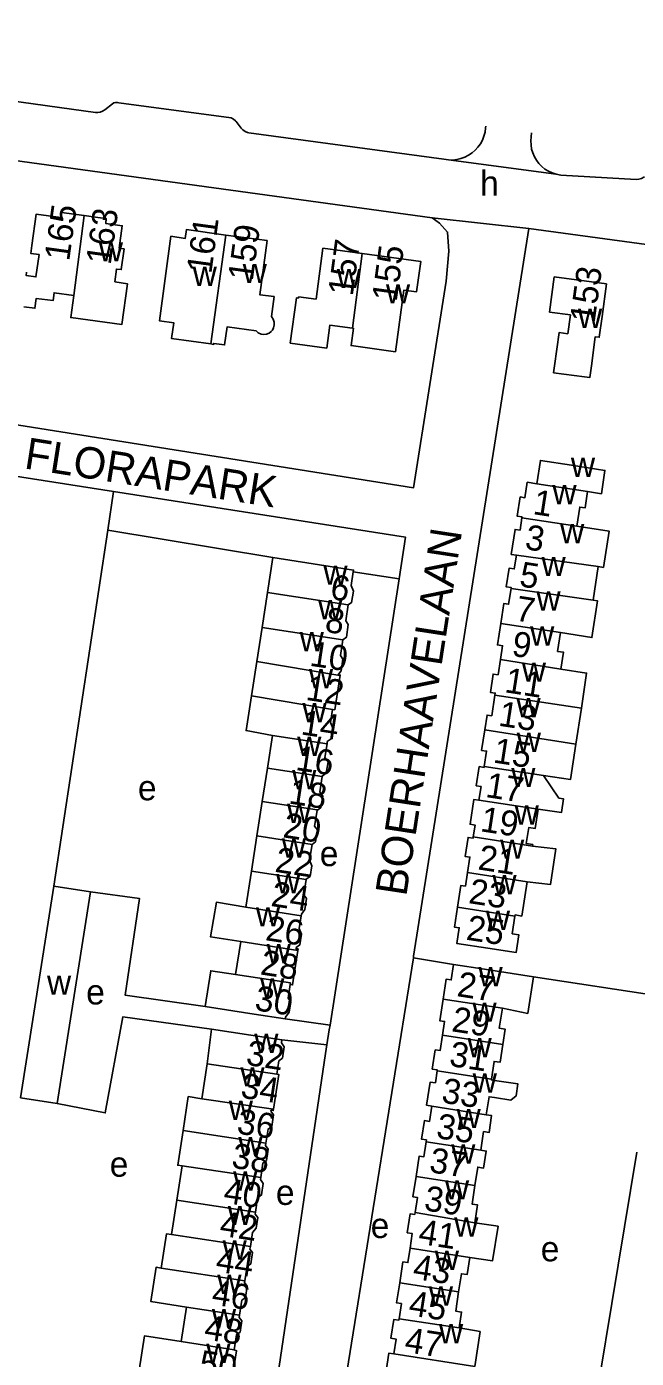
# Model space of a CAD drawing. Extents: x 161093 to 163177, y 379000 to 380904.
# Drawn here: x 161971.7 to 162069, y 380591.7 to 380804.1 of the extents above; entities that cross this region are included whole.
import ezdxf

# ---------------------------------------------------------------- set-up
doc = ezdxf.new("R2010")
doc.units = 0
for name, color, linetype in [('BLT_Basislijn', 7, 'Continuous'), ('BLT_Bebouwing', 7, 'Continuous'), ('BLT_Centroide', 7, 'Continuous'), ('BLT_Huisnummer', 7, 'Continuous'), ('BLT_Huisnummer_ tussenligend', 7, 'Continuous'), ('BLT_Onderverdeling_panden', 7, 'Continuous'), ('BLT_Straatnaam', 7, 'Continuous'), ('BLT_Vlakafsluiter', 7, 'Continuous')]:
    doc.layers.add(name, color=color, linetype=linetype)

msp = doc.modelspace()

# ---------------------------------------------------------------- linework, layer by layer
at = {"layer": 'BLT_Basislijn'}
for p, q in [((161944, 380795.73), (161982.7, 380790.46)), ((161985.43, 380791.84), (161984.2, 380790.88)), ((161986.42, 380791.99), (162004.35, 380789.6)), ((162005.15, 380788.99), (162005.94, 380787.96)), ((162045.01, 380788.28), (162044.96, 380787.97)), ((162052.3, 380787.21), (162052.25, 380786.56)), ((161984.69, 380723.8), (161985.62, 380729.97)), ((162011, 380719.43), (161984.69, 380723.8)), ((162031.18, 380716.05), (162023.85, 380717.15)), ((162020.14, 380644.86), (162031.18, 380716.05)), ((162039.85, 380654.53), (162033.44, 380655.58)), ((162072.89, 380649.45), (162052.6, 380652.57)), ((162012.98, 380645.84), (162020.14, 380644.86)), ((162012.46, 380642.49), (162019.64, 380641.72))]:
    msp.add_line(p, q, dxfattribs=at)
for points in [[(161815.82, 380804.14), (161900, 380793.04), (161955.5, 380784.75), (162036.45, 380773.62)], [(161985.43, 380791.84), (161985.66, 380791.98), (161985.92, 380792.06), (161986.2, 380792.06), (161986.42, 380791.99)], [(161982.7, 380790.46), (161983.09, 380790.44), (161983.47, 380790.5), (161983.83, 380790.64), (161984.2, 380790.88)], [(162004.35, 380789.6), (162004.73, 380789.37), (162005.06, 380789.09), (162005.15, 380788.99)], [(162005.94, 380787.96), (162006.25, 380787.66), (162006.61, 380787.41), (162007, 380787.24), (162007.19, 380787.18)], [(162007.19, 380787.18), (162038.29, 380782.98), (162039.05, 380782.87)], [(162044.96, 380787.97), (162044.87, 380787.31), (162044.7, 380786.67), (162044.46, 380786.05), (162044.14, 380785.46), (162043.75, 380784.92), (162043.3, 380784.43), (162042.8, 380783.99), (162042.24, 380783.62), (162041.65, 380783.32), (162041.02, 380783.09), (162040.38, 380782.94), (162039.71, 380782.86), (162039.05, 380782.87)], [(162052.25, 380786.56), (162052.19, 380785.91), (162052.21, 380785.26), (162052.31, 380784.61), (162052.49, 380783.98), (162052.75, 380783.38), (162053.08, 380782.82), (162053.47, 380782.3), (162053.93, 380781.83), (162054.43, 380781.42), (162054.99, 380781.07), (162055.58, 380780.8), (162056.2, 380780.6)], [(162056.2, 380780.6), (162056.95, 380780.46), (162068.97, 380779.73)], [(162068.97, 380779.73), (162069.4, 380779.78), (162069.83, 380779.9), (162070.22, 380780.1), (162070.33, 380780.18)], [(162036.45, 380773.62), (162037.62, 380772.81), (162038.9, 380771.36), (162039.11, 380768.34), (162038.66, 380763.52), (162033.44, 380730.54), (161945.64, 380744.48), (161940.61, 380712.05), (161930.4, 380713.71)], [(162051.87, 380771.94), (162033.48, 380655.83), (162033.44, 380655.58)], [(162140.7, 380759.86), (162051.87, 380771.94)], [(161957.99, 380734.3), (161985.62, 380729.97)], [(161985.62, 380729.97), (162032.21, 380722.67), (162031.18, 380716.05)], [(161984.69, 380723.8), (161976.06, 380667.03)], [(162000.24, 380647.8), (161987.44, 380649.63), (161989.76, 380665.04), (161981.9, 380666.11)], [(162033.44, 380655.58), (162019.61, 380569.67), (162019.47, 380568.79)], [(162001.24, 380644.21), (161987.08, 380646.16), (161984.29, 380630.85), (161976.58, 380632.33)], [(162020.14, 380644.86), (162020.02, 380644.09), (162019.64, 380641.72)], [(162009, 380569.91), (162019.42, 380640.32), (162019.64, 380641.72)], [(162039.84, 380567.66), (162059.15, 380564.39), (162069.07, 380624.57)]]:
    msp.add_lwpolyline(points, dxfattribs=at)
at = {"layer": 'BLT_Bebouwing'}
for p, q in [((162011, 380719.43), (162010.15, 380713.85)), ((162010.15, 380713.85), (162009.29, 380708.3)), ((162009.29, 380708.3), (162008.46, 380702.86)), ((162008.46, 380702.86), (162007.61, 380697.37)), ((162020.93, 380695.15), (162020.54, 380695.21)), ((162010.94, 380691.07), (162010.14, 380685.85)), ((162010.14, 380685.85), (162009.32, 380680.51)), ((162009.32, 380680.51), (162008.48, 380675.02)), ((162008.48, 380675.02), (162007.62, 380669.43)), ((162007.62, 380669.43), (162006.73, 380663.65)), ((161976.06, 380667.03), (161970.74, 380633.25)), ((161981.9, 380666.11), (161976.06, 380667.03)), ((161976.58, 380632.33), (161981.9, 380666.11)), ((162005.89, 380658.16), (162005.08, 380652.91)), ((162000.54, 380638.68), (162001.24, 380644.21)), ((161999.69, 380633.11), (162000.54, 380638.68)), ((161970.74, 380633.25), (161976.58, 380632.33)), ((161995.7, 380616.91), (161994.86, 380611.44)), ((161996.38, 380594.36), (161997.22, 380599.86))]:
    msp.add_line(p, q, dxfattribs=at)
for points in [[(161971.71, 380764.94), (161971.64, 380764.44), (161973.22, 380764.22), (161973.72, 380767.78), (161972.39, 380767.97), (161972.57, 380769.23), (161973.26, 380774.23), (161977.2, 380773.68), (161977.31, 380774.48), (161980.93, 380773.99)], [(161980.93, 380773.99), (161983.08, 380773.7), (161984.45, 380773.51), (161984.35, 380772.74), (161986.98, 380772.37), (161986.48, 380768.8), (161987.29, 380768.68), (161986.83, 380765.37), (161986.07, 380765.47), (161985.79, 380763.41)], [(162003.5, 380770.88), (161997.24, 380771.75), (161997.05, 380770.36), (161994.76, 380770.7), (161992.94, 380757.2), (161995.2, 380756.89), (161994.85, 380754.36), (162001.15, 380753.51)], [(162003.5, 380770.88), (162010.11, 380770.01), (162008.94, 380761.37), (162011.22, 380761.07), (162010.79, 380757.88), (162011.08, 380757.45), (162011.22, 380757.01), (162011.25, 380756.57), (162011.13, 380756.1), (162010.95, 380755.73), (162010.73, 380755.51), (162010.42, 380755.25), (162010.01, 380755.09), (162009.57, 380755.03), (162009.14, 380755.09), (162008.7, 380755.31), (162008.37, 380755.6), (162003.71, 380756.23), (162003.32, 380753.36), (162001.58, 380753.59), (162001.56, 380753.45), (162001.15, 380753.51)], [(162023.72, 380756.03), (162020.1, 380756.5), (162019.62, 380752.86), (162013.79, 380753.65), (162014.77, 380760.87), (162015.1, 380760.83), (162015.12, 380761.03), (162017.93, 380760.66), (162019.02, 380768.78), (162025.29, 380767.94)], [(162025.29, 380767.94), (162034.63, 380766.69), (162033.96, 380761.83), (162031.92, 380762.11), (162030.58, 380752.28), (162023.51, 380753.26), (162023.87, 380756.02), (162023.72, 380756.03)], [(162064.25, 380763.08), (162063.54, 380757.91), (162063.09, 380754.58), (162062.47, 380754.66), (162061.84, 380750), (162061.59, 380748.16), (162060.77, 380748.27), (162055.81, 380748.93), (162055.96, 380750), (162056.68, 380755.32), (162058.08, 380755.13), (162058.49, 380758.15), (162055.16, 380758.61), (162055.92, 380764.21), (162064.25, 380763.08)], [(161979.24, 380761.24), (161976.12, 380761.68), (161975.95, 380760.42), (161973.27, 380760.79), (161973.05, 380759.2), (161971.3, 380759.44)], [(161979.24, 380761.24), (161978.76, 380757.72), (161986.91, 380756.6), (161987.81, 380763.13), (161985.79, 380763.41)], [(162053.13, 380731.22), (162053.71, 380734.93), (162058.65, 380734.17), (162064.01, 380733.34), (162063.44, 380729.62), (162061.24, 380729.96)], [(162050.77, 380725.8), (162050.79, 380725.92), (162050.01, 380726.04), (162050.48, 380729.1), (162051.23, 380728.98), (162051.61, 380731.45), (162053.13, 380731.22)], [(162061.24, 380729.96), (162060.85, 380727.37), (162059.99, 380727.5), (162059.52, 380724.44)], [(162049.87, 380719.81), (162049.06, 380719.93), (162049.68, 380723.94), (162050.46, 380723.82), (162050.77, 380725.8)], [(162059.52, 380724.44), (162064.66, 380723.65), (162063.77, 380717.86), (162062.95, 380717.99)], [(162023.85, 380717.15), (162023.89, 380717.45), (162011, 380719.43)], [(162049.02, 380714.48), (162049.05, 380714.64), (162048.27, 380714.76), (162048.73, 380717.75), (162049.53, 380717.62), (162049.87, 380719.81)], [(162023.85, 380717.15), (162023.52, 380714.98), (162023.87, 380714.08), (162023.59, 380712.26), (162023.05, 380711.87)], [(162062.95, 380717.99), (162062.13, 380712.62)], [(162047.39, 380708.94), (162047.88, 380712.11), (162048.64, 380711.99), (162049.02, 380714.48)], [(162062.13, 380712.62), (162062.84, 380712.51), (162061.93, 380706.67), (162056.93, 380707.46)], [(162023.05, 380711.87), (162022.65, 380709.33), (162023.06, 380708.77), (162022.75, 380706.73), (162022.18, 380706.31)], [(162047.34, 380703.16), (162047.68, 380705.36), (162046.86, 380705.49), (162047.39, 380708.94)], [(162022.18, 380706.31), (162021.79, 380703.8), (162022.21, 380703.24), (162021.92, 380701.39), (162021.4, 380700.7)], [(162056.97, 380701.63), (162057.41, 380704.32), (162056.46, 380704.47), (162056.93, 380707.46)], [(162046.45, 380697.5), (162046.5, 380697.81), (162045.72, 380697.93), (162046.17, 380700.85), (162046.96, 380700.73), (162047.34, 380703.16)], [(162021.4, 380700.7), (162021.78, 380700.69), (162020.93, 380695.15)], [(162060.24, 380695.42), (162061.08, 380701), (162056.97, 380701.63)], [(162007.61, 380697.37), (162006.76, 380691.83), (162010.94, 380691.07)], [(162044.82, 380691.96), (162045.19, 380694.32), (162045.94, 380694.21), (162046.45, 380697.5)], [(162020.54, 380695.21), (162020.23, 380693.14), (162020.58, 380692.23), (162020.32, 380690.51), (162019.71, 380690.07), (162019.66, 380689.73)], [(162059.37, 380689.68), (162060.24, 380695.42)], [(162044.74, 380686.13), (162045.12, 380688.56), (162044.32, 380688.68), (162044.82, 380691.96)], [(162019.66, 380689.73), (162019.32, 380687.53), (162019.82, 380686.85), (162019.54, 380685.04), (162018.88, 380684.56), (162018.88, 380684.51)], [(162054.18, 380684.68), (162058.51, 380684.02), (162059.37, 380689.68)], [(162043.9, 380680.72), (162044.23, 380682.91), (162043.48, 380683.03), (162043.95, 380686.08), (162044.72, 380685.97), (162044.74, 380686.13)], [(162018.88, 380684.51), (162018.5, 380682.04), (162018.97, 380681.39), (162018.69, 380679.56), (162018.07, 380679.1)], [(162053.34, 380679.32), (162057.06, 380678.75), (162057.4, 380680.94), (162056.66, 380681.05), (162054.18, 380684.68)], [(162042.99, 380674.86), (162043.28, 380676.76), (162042.49, 380676.88), (162043.1, 380680.84), (162043.9, 380680.72)], [(162018.07, 380679.1), (162017.68, 380676.58), (162018.13, 380675.98), (162017.84, 380674.1), (162017.27, 380673.68)], [(162052.44, 380673.39), (162052.48, 380673.65), (162051.45, 380673.8), (162051.84, 380676.36), (162052.86, 380676.2), (162053.34, 380679.32)], [(162042.08, 380669.21), (162042.45, 380671.64), (162041.7, 380671.75), (162042.16, 380674.79), (162042.96, 380674.67), (162042.99, 380674.86)], [(162017.27, 380673.68), (162016.88, 380671.18), (162017.24, 380670.27), (162016.97, 380668.57), (162016.36, 380668.11), (162016.36, 380668.09)], [(162051.59, 380667.73), (162055.31, 380667.27), (162056.18, 380672.95), (162052.44, 380673.39)], [(162016.36, 380668.09), (162015.97, 380665.61), (162016.4, 380665.03), (162016.13, 380663.27), (162015.57, 380662.57), (162015.53, 380662.3)], [(162040.49, 380663.66), (162041.02, 380667.14), (162041.74, 380667.03), (162042.08, 380669.21)], [(162049.64, 380662.24), (162049.67, 380662.42), (162050.74, 380662.25), (162051.59, 380667.73)], [(162006.73, 380663.65), (162002.01, 380664.44), (162001.06, 380658.95), (162005.89, 380658.16)], [(162049.64, 380662.24), (162049.21, 380659.42), (162050.26, 380659.26), (162049.82, 380656.42), (162045.31, 380657.11), (162040.37, 380657.87), (162040.75, 380660.37), (162040, 380660.49), (162040.49, 380663.66)], [(162015.53, 380662.3), (162015.22, 380660.27), (162015.58, 380659.34), (162015.32, 380657.64), (162014.75, 380657.22), (162014.72, 380657.04), (162015.04, 380656.99), (162015, 380656.76)], [(162015, 380656.76), (162014.16, 380651.25), (162013.79, 380651.34)], [(162005.08, 380652.91), (162001.11, 380653.52), (162000.24, 380647.8)], [(162039.85, 380654.53), (162039.47, 380652.06), (162038.68, 380652.18), (162038.19, 380649)], [(162052.6, 380652.57), (162044.79, 380653.77), (162039.85, 380654.53)], [(162013.79, 380651.34), (162013.45, 380649.17), (162013.9, 380648.57), (162013.64, 380646.89), (162013.02, 380646.12), (162012.98, 380645.84)], [(162047.64, 380647.55), (162051.69, 380646.7), (162052.6, 380652.57)], [(162038.19, 380649), (162037.66, 380645.55), (162038.42, 380645.43), (162038.09, 380643.23)], [(162000.24, 380647.8), (162008.04, 380646.6), (162012.98, 380645.84)], [(162047.71, 380641.74), (162048.09, 380644.2), (162047.14, 380644.35), (162047.64, 380647.55)], [(162001.24, 380644.21), (162007.52, 380643.25), (162012.46, 380642.49)], [(162012.46, 380642.49), (162012.38, 380642), (162012.83, 380641.39), (162012.55, 380639.58), (162011.96, 380639.14), (162011.63, 380637)], [(162038.09, 380643.23), (162037.71, 380640.78), (162036.93, 380640.9), (162036.46, 380637.83), (162037.26, 380637.7), (162037.24, 380637.56)], [(162045.89, 380636.23), (162046.33, 380639.05), (162047.27, 380638.91), (162047.71, 380641.74)], [(162011.63, 380637), (162011.97, 380636.98), (162011.12, 380631.45)], [(162037.24, 380637.56), (162036.95, 380635.65), (162036.14, 380635.77), (162035.55, 380632.07), (162036.36, 380631.91)], [(162045.08, 380630.56), (162045.52, 380633.42), (162046.36, 380633.29), (162048.97, 380632.89), (162049.84, 380633.55), (162050.13, 380635.46), (162046.77, 380635.97), (162045.88, 380636.11), (162045.89, 380636.23)], [(161996.69, 380628.05), (161997.52, 380633.45), (161999.69, 380633.11)], [(162036.36, 380631.91), (162035.99, 380629.49), (162035.21, 380629.61), (162034.76, 380626.65), (162035.53, 380626.53), (162035.49, 380626.25)], [(162011.12, 380631.45), (162011.08, 380631.22), (162010.73, 380631.27), (162010.71, 380631.1), (162011.12, 380630.53), (162010.84, 380628.68), (162010.25, 380628.25), (162009.91, 380626.02)], [(162044.18, 380624.91), (162044.63, 380627.85), (162045.51, 380627.71), (162045.93, 380630.42), (162045.08, 380630.56)], [(161996.55, 380622.39), (161995.84, 380622.5), (161996.69, 380628.05)], [(162009.91, 380626.02), (162009.85, 380625.64), (162010.29, 380625.04), (162010.02, 380623.27), (162009.43, 380622.84), (162009.08, 380620.52)], [(162035.49, 380626.25), (162035.12, 380623.84), (162034.37, 380623.96), (162033.87, 380620.71)], [(162043.26, 380619.26), (162043.71, 380622.19), (162044.64, 380622.04), (162045.06, 380624.76), (162044.18, 380624.91)], [(161995.7, 380616.91), (161996.55, 380622.39)], [(162009.08, 380620.52), (162009.03, 380620.22), (162009.49, 380619.58), (162009.21, 380617.77), (162008.59, 380617.31), (162008.24, 380615.03)], [(162033.87, 380620.71), (162033.37, 380617.46), (162034.08, 380617.35), (162033.71, 380614.94)], [(162043.26, 380613.33), (162043.69, 380616.15), (162042.81, 380616.29), (162043.26, 380619.26)], [(162008.24, 380615.03), (162008.2, 380614.71), (162008.61, 380614.15), (162008.35, 380612.47), (162007.77, 380611.74), (162007.43, 380609.53)], [(162033.71, 380614.94), (162033.67, 380614.65), (162032.93, 380614.76), (162032.46, 380611.72), (162033.27, 380611.59), (162032.92, 380609.27)], [(162042.43, 380607.8), (162046.08, 380607.25), (162046.96, 380612.77), (162043.26, 380613.33)], [(161993.22, 380606.09), (161994.06, 380611.56), (161994.86, 380611.44)], [(162007.43, 380609.53), (162007.37, 380609.1), (162007.76, 380608.57), (162007.48, 380606.76), (162006.92, 380606.34), (162006.56, 380604.04)], [(162032.92, 380609.27), (162032.56, 380606.96), (162031.78, 380607.08), (162031.26, 380603.73)], [(162040.66, 380602.28), (162041.11, 380605.19), (162042.01, 380605.05), (162042.43, 380607.8)], [(161997.22, 380599.86), (161991.56, 380600.74), (161992.4, 380606.21), (161993.22, 380606.09)], [(162006.56, 380604.04), (162006.52, 380603.76), (162006.94, 380603.18), (162006.67, 380601.39), (162006.06, 380600.95), (162005.69, 380598.56)], [(162031.26, 380603.73), (162030.77, 380600.54), (162031.52, 380600.43), (162031.15, 380598.01)], [(162040.74, 380596.54), (162041.13, 380599.07), (162040.19, 380599.22), (162040.66, 380602.28)], [(162005.69, 380598.56), (162005.64, 380598.21), (162006.05, 380597.65), (162005.78, 380595.88), (162005.21, 380595.46), (162004.84, 380593.07)], [(162031.15, 380598.01), (162031.11, 380597.75), (162030.32, 380597.87), (162029.86, 380594.9), (162030.68, 380594.77), (162030.31, 380592.38)], [(162043.22, 380590.39), (162044.08, 380595.95), (162040.74, 380596.54)], [(161992.58, 380589.37), (161989.71, 380589.81), (161990.55, 380595.29), (161996.38, 380594.36)], [(162004.84, 380593.07), (162005.24, 380592.91), (162004.36, 380587.52)], [(162030.31, 380592.38), (162029.52, 380592.5), (162028.93, 380588.62), (162029.68, 380588.51), (162029.41, 380586.75)]]:
    msp.add_lwpolyline(points, dxfattribs=at)
at = {"layer": 'BLT_Onderverdeling_panden'}
for p, q in [((161979.24, 380761.24), (161980.93, 380773.99)), ((162003.5, 380770.88), (162001.15, 380753.51)), ((162025.29, 380767.94), (162023.72, 380756.03)), ((162053.13, 380731.22), (162061.24, 380729.96)), ((162059.52, 380724.44), (162050.77, 380725.8)), ((162062.95, 380717.99), (162049.87, 380719.81)), ((162023.05, 380711.87), (162010.15, 380713.85)), ((162062.13, 380712.62), (162049.02, 380714.48)), ((162022.18, 380706.31), (162009.29, 380708.3)), ((162056.93, 380707.46), (162047.39, 380708.94)), ((162021.4, 380700.7), (162008.46, 380702.86)), ((162056.97, 380701.63), (162047.34, 380703.16)), ((162020.54, 380695.21), (162007.61, 380697.37)), ((162060.24, 380695.42), (162046.45, 380697.5)), ((162059.37, 380689.68), (162044.82, 380691.96)), ((162019.66, 380689.73), (162010.94, 380691.07)), ((162018.88, 380684.51), (162010.14, 380685.85)), ((162053.34, 380679.32), (162043.9, 380680.72)), ((162017.27, 380673.68), (162008.48, 380675.02)), ((162052.44, 380673.39), (162042.99, 380674.86)), ((162016.36, 380668.09), (162007.62, 380669.43)), ((162051.59, 380667.73), (162042.08, 380669.21)), ((162015.53, 380662.3), (162006.73, 380663.65)), ((162049.64, 380662.24), (162040.49, 380663.66)), ((162015, 380656.76), (162005.89, 380658.16)), ((162047.64, 380647.55), (162038.19, 380649)), ((162047.71, 380641.74), (162038.09, 380643.23)), ((162011.63, 380637), (162000.54, 380638.68)), ((162045.89, 380636.23), (162037.24, 380637.56)), ((162011.12, 380631.45), (161999.69, 380633.11)), ((162045.08, 380630.56), (162036.36, 380631.91)), ((162009.91, 380626.02), (161996.69, 380628.05)), ((162044.18, 380624.91), (162035.49, 380626.25)), ((162009.08, 380620.52), (161996.55, 380622.39)), ((162043.26, 380619.26), (162033.87, 380620.71)), ((162008.24, 380615.03), (161995.7, 380616.91)), ((162043.26, 380613.33), (162033.71, 380614.94)), ((162007.43, 380609.53), (161994.86, 380611.44)), ((162042.43, 380607.8), (162032.92, 380609.27)), ((162006.56, 380604.04), (161993.22, 380606.09)), ((162040.66, 380602.28), (162031.26, 380603.73)), ((162005.69, 380598.56), (161997.22, 380599.86)), ((162040.74, 380596.54), (162031.15, 380598.01)), ((162004.84, 380593.07), (161996.38, 380594.36)), ((162043.22, 380590.39), (162030.31, 380592.38))]:
    msp.add_line(p, q, dxfattribs=at)
for points in [[(162054.18, 380684.68), (162044.74, 380686.13)], [(162018.07, 380679.1), (162018.08, 380679.17), (162009.32, 380680.51)], [(162013.79, 380651.34), (162013.82, 380651.57), (162005.08, 380652.91)]]:
    msp.add_lwpolyline(points, dxfattribs=at)
at = {"layer": 'BLT_Vlakafsluiter'}
for p, q in [((162056.2, 380780.6), (162039.05, 380782.87)), ((162036.45, 380773.62), (162051.87, 380771.94))]:
    msp.add_line(p, q, dxfattribs=at)

# ---------------------------------------------------------------- texts
at = {"layer": 'BLT_Centroide'}
for s, p in [('h', (162044.09, 380777.15)), ('w', (161983.25, 380766.67)), ('w', (161998.22, 380762.77)), ('w', (162006.2, 380763.22)), ('w', (162021.22, 380762.42)), ('w', (162029.06, 380759.97)), ('w', (162059.7, 380756.05)), ('w', (162058.57, 380732.28)), ('w', (162055.62, 380727.94)), ('w', (162056.85, 380721.72)), ('w', (162053.88, 380716.47)), ('w', (162019.08, 380715.09)), ('w', (162018.24, 380709.59)), ('w', (162053.07, 380710.97)), ('w', (162052.06, 380705.38)), ('w', (162015.3, 380704.5)), ('w', (162050.74, 380699.62)), ('w', (162016.77, 380698.59)), ('w', (162015.73, 380693.16)), ('w', (162049.87, 380693.94)), ('w', (162049.93, 380688.41)), ('w', (162014.9, 380687.78)), ('w', (162014.09, 380682.47)), ('w', (162049.05, 380682.81)), ('e', (161989.49, 380680.71)), ('w', (162013.28, 380677.09)), ('w', (162049.59, 380676.84)), ('w', (162012.44, 380671.56)), ('w', (162047.27, 380671.38)), ('e', (162018.5, 380670.21)), ('w', (162011.54, 380665.88)), ('w', (162046.04, 380665.72)), ('w', (162008.3, 380660.59)), ('w', (162045, 380660.03)), ('w', (162010.02, 380654.72)), ('w', (162043.82, 380651.03)), ('w', (161974.98, 380649.69)), ('e', (161981.23, 380648.14)), ('w', (162008.99, 380649.25)), ('w', (162042.86, 380645.38)), ('w', (162008.05, 380640.41)), ('w', (162042.08, 380639.72)), ('w', (162005.83, 380635.06)), ('w', (162042.9, 380634.06)), ('w', (162003.98, 380629.72)), ('w', (162040.33, 380628.41)), ('w', (162005.51, 380623.91)), ('w', (162039.47, 380622.75)), ('e', (161984.99, 380620.66)), ('w', (162004.69, 380618.44)), ('e', (162011.5, 380616.16)), ('w', (162038.48, 380617.03)), ('w', (162003.82, 380612.94)), ('e', (162026.63, 380610.88)), ('w', (162039.95, 380611.09)), ('w', (162002.99, 380607.44)), ('w', (162036.85, 380605.78)), ('e', (162053.76, 380607.16)), ('w', (162002.15, 380601.94)), ('w', (162035.9, 380600.09)), ('w', (162001.29, 380596.47)), ('w', (162037.52, 380594.09)), ('w', (162000.39, 380590.94))]:
    msp.add_text(s, height=4, dxfattribs=at).set_placement(p)
at = {"layer": 'BLT_Huisnummer'}
for s, rotation, p in [('165', 82.1094, (161978.52, 380766.63)), ('163', 82.1023, (161985.14, 380766.03)), ('161', 82.3132, (162001.2, 380764.61)), ('159', 82.3092, (162007.8, 380763.45)), ('157', 82.3009, (162023.76, 380761.05)), ('155', 82.3158, (162030.77, 380760.15)), ('153', 82.2551, (162062.35, 380756.75)), ('1', 351.1717, (162052.38, 380726.39)), ('5', 351.1719, (162050.21, 380714.87)), ('6', 351.2741, (162020.02, 380712.85)), ('9', 351.1733, (162049, 380703.79)), ('10', 351.2792, (162016.76, 380702.2)), ('13', 351.177, (162046.88, 380692.63)), ('14', 351.2785, (162015.37, 380691.24)), ('17', 351.2573, (162044.82, 380681.25)), ('18', 351.2759, (162013.41, 380680.22)), ('22', 351.2773, (162011.21, 380669.32)), ('21', 351.2418, (162043.61, 380669.7)), ('26', 351.276, (162009.71, 380658.41)), ('25', 351.2494, (162041.73, 380658.49)), ('27', 351.2494, (162040.25, 380649.48)), ('30', 351.2687, (162007.98, 380647.25)), ('32', 351.2748, (162006.59, 380638.53)), ('31', 351.2489, (162039.02, 380638.36)), ('36', 351.2752, (162005.12, 380627.58)), ('35', 351.2479, (162036.95, 380626.85)), ('40', 351.2791, (162003, 380616.53)), ('39', 351.2464, (162035.01, 380615.33)), ('44', 351.2772, (162001.76, 380605.55)), ('43', 351.243, (162033.22, 380604.4)), ('48', 351.2719, (161999.92, 380594.74)), ('47', 351.2479, (162031.89, 380592.72))]:
    msp.add_text(s, height=4, rotation=rotation, dxfattribs=at).set_placement(p)
at = {"layer": 'BLT_Huisnummer_ tussenligend'}
for s, rotation, p in [('3', 351.1717, (162051.09, 380720.8)), ('7', 351.1719, (162049.56, 380709.42)), ('8', 351.2741, (162019.18, 380707.61)), ('12', 351.2792, (162016.14, 380696.75)), ('11', 351.1733, (162047.87, 380697.97)), ('16', 351.2785, (162014.53, 380685.57)), ('15', 351.177, (162046.04, 380686.76)), ('20', 351.2759, (162012.49, 380674.82)), ('19', 351.2573, (162043.99, 380675.79)), ('23', 351.2418, (162042.12, 380664.32)), ('24', 351.2773, (162010.57, 380663.87)), ('28', 351.276, (162008.88, 380652.95)), ('29', 351.2489, (162039.41, 380643.88)), ('34', 351.2748, (162005.74, 380633.29)), ('33', 351.2479, (162037.79, 380632.51)), ('38', 351.2752, (162004.29, 380622.12)), ('37', 351.2464, (162035.84, 380621.41)), ('42', 351.2791, (162002.38, 380611.29)), ('41', 351.243, (162034.09, 380609.99)), ('46', 351.2772, (162001.13, 380600.3)), ('45', 351.2479, (162032.54, 380598.59)), ('50', 351.2719, (161999.07, 380589.08))]:
    msp.add_text(s, height=4, rotation=rotation, dxfattribs=at).set_placement(p)
at = {"layer": 'BLT_Straatnaam'}
for s, rotation, p in [('FLORAPARK', 351.1079, (161971.2, 380733.68)), ('BOERHAAVELAAN', 81.312, (162032.3, 380665.27))]:
    msp.add_text(s, height=5, rotation=rotation, dxfattribs=at).set_placement(p)

doc.saveas('drawing.dxf')
